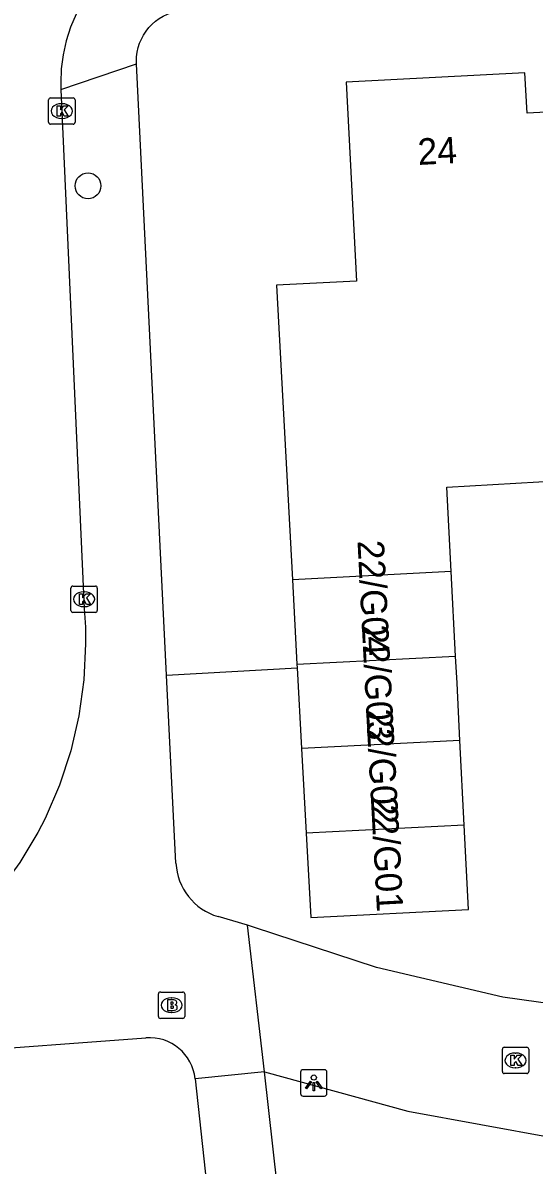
# Model space of a CAD drawing. Extents: x 161253 to 161848, y 384872 to 385383.
# Drawn here: x 161394.3 to 161413.67, y 385296.1 to 385339.43 of the extents above; entities that cross this region are included whole.
import ezdxf

# ---------------------------------------------------------------- set-up
doc = ezdxf.new("R2010")
doc.units = 0
for name, color, linetype in [('IMGEO_Boom', 7, 'Continuous'), ('IMGEO_Brandkraan', 7, 'Continuous'), ('IMGEO_Erf', 7, 'Continuous'), ('IMGEO_Kolk', 7, 'Continuous'), ('IMGEO_Lichtpunt', 7, 'Continuous'), ('IMGEO_Pand', 7, 'Continuous'), ('IMGEO_Pand_nummerreeks', 7, 'Continuous'), ('IMGEO_Rijbaan_lokaal_open', 7, 'Continuous'), ('IMGEO_Voetpad_open', 7, 'Continuous')]:
    doc.layers.add(name, color=color, linetype=linetype)

msp = doc.modelspace()

# ---------------------------------------------------------------- linework, layer by layer
at = {"layer": 'IMGEO_Boom'}
msp.add_circle((161396.765, 385333.248), 0.489, dxfattribs=at)
at = {"layer": 'IMGEO_Brandkraan'}
for p, q in [((161399.432, 385301.745), (161399.432, 385302.597)), ((161399.507, 385302.671), (161400.359, 385302.671)), ((161399.92, 385302.451), (161399.945, 385302.451)), ((161400.433, 385302.597), (161400.433, 385301.745)), ((161400.359, 385301.671), (161399.507, 385301.671)), ((161399.943, 385301.891), (161399.918, 385301.891))]:
    msp.add_line(p, q, dxfattribs=at)
for points in [[(161399.432, 385301.745), (161399.432, 385302.597)], [(161399.507, 385302.671), (161400.359, 385302.671)], [(161400.433, 385302.597), (161400.433, 385301.745)], [(161399.78, 385302.371), (161399.78, 385301.971), (161399.993, 385301.971)], [(161400.011, 385302.371), (161399.78, 385302.371)], [(161399.959, 385302.29), (161399.905, 385302.29), (161399.905, 385302.214)], [(161399.905, 385302.214), (161399.958, 385302.214)], [(161399.967, 385302.138), (161399.905, 385302.138), (161399.905, 385302.057)], [(161399.905, 385302.057), (161399.967, 385302.057)], [(161400.359, 385301.671), (161399.507, 385301.671)]]:
    msp.add_lwpolyline(points, dxfattribs=at)
for centre, radius, start, end in [((161399.509, 385302.595), 0.0765, 91.552, 178.448), ((161399.509, 385302.595), 0.0765, 91.552, 178.448), ((161400.357, 385302.595), 0.0765, 1.552, 88.448), ((161400.357, 385302.595), 0.0765, 1.552, 88.448), ((161399.96, 385302.252), 0.0379, 267.8285, 90.9355), ((161399.968, 385302.097), 0.0404, 269.8759, 90.5077), ((161399.999, 385302.222), 0.251, 268.6676, 293.5347), ((161400.015, 385302.226), 0.145, 59.4692, 91.5367), ((161400.04, 385302.273), 0.0922, 285.5137, 58.1501), ((161400.045, 385302.081), 0.105, 301.3115, 78.989), ((161399.509, 385301.747), 0.0765, 181.552, 268.448), ((161399.509, 385301.747), 0.0765, 181.552, 268.448), ((161400.357, 385301.747), 0.0765, 271.552, 358.448), ((161400.357, 385301.747), 0.0765, 271.552, 358.448)]:
    msp.add_arc(centre, radius, start, end, dxfattribs=at)
for centre, major_axis, ratio, start_param, end_param in [((161399.919, 385302.171), (-0.387, 0.002), 0.722429, 4.712389, 7.853982), ((161399.944, 385302.171), (-0.39, 0.002), 0.717154, 1.570796, 4.712389)]:
    msp.add_ellipse(centre, major_axis=major_axis, ratio=ratio, start_param=start_param, end_param=end_param, dxfattribs=at)
at = {"layer": 'IMGEO_Erf'}
msp.add_lwpolyline([(161399.745, 385314.686), (161404.692, 385314.964)], dxfattribs=at)
at = {"layer": 'IMGEO_Kolk'}
for p, q in [((161395.273, 385335.659), (161395.273, 385336.511)), ((161395.348, 385336.585), (161396.2, 385336.585)), ((161395.761, 385336.365), (161395.786, 385336.365)), ((161396.274, 385336.511), (161396.274, 385335.659)), ((161395.784, 385335.805), (161395.759, 385335.805)), ((161396.2, 385335.585), (161395.348, 385335.585)), ((161396.191, 385318.068), (161397.043, 385318.068)), ((161396.116, 385317.142), (161396.116, 385317.994)), ((161396.604, 385317.848), (161396.629, 385317.848)), ((161397.117, 385317.994), (161397.117, 385317.142)), ((161396.627, 385317.288), (161396.602, 385317.288)), ((161397.043, 385317.068), (161396.191, 385317.068)), ((161412.466, 385299.651), (161412.466, 385300.503)), ((161412.541, 385300.577), (161413.393, 385300.577)), ((161412.954, 385300.357), (161412.979, 385300.357)), ((161413.467, 385300.503), (161413.467, 385299.651)), ((161413.393, 385299.577), (161412.541, 385299.577)), ((161412.977, 385299.797), (161412.952, 385299.797))]:
    msp.add_line(p, q, dxfattribs=at)
for points in [[(161395.273, 385335.659), (161395.273, 385336.511)], [(161395.348, 385336.585), (161396.2, 385336.585)], [(161395.594, 385336.285), (161395.717, 385336.285), (161395.717, 385336.134), (161395.847, 385336.285), (161396.011, 385336.285), (161395.865, 385336.134), (161396.018, 385335.885), (161395.866, 385335.885), (161395.781, 385336.049), (161395.717, 385335.982), (161395.717, 385335.885), (161395.594, 385335.885), (161395.594, 385336.285)], [(161396.274, 385336.511), (161396.274, 385335.659)], [(161396.2, 385335.585), (161395.348, 385335.585)], [(161396.191, 385318.068), (161397.043, 385318.068)], [(161396.116, 385317.142), (161396.116, 385317.994)], [(161396.437, 385317.768), (161396.56, 385317.768), (161396.56, 385317.617), (161396.69, 385317.768), (161396.854, 385317.768), (161396.708, 385317.617), (161396.861, 385317.368), (161396.709, 385317.368), (161396.624, 385317.532), (161396.56, 385317.465), (161396.56, 385317.368), (161396.437, 385317.368), (161396.437, 385317.768)], [(161397.117, 385317.994), (161397.117, 385317.142)], [(161397.043, 385317.068), (161396.191, 385317.068)], [(161412.466, 385299.651), (161412.466, 385300.503)], [(161412.541, 385300.577), (161413.393, 385300.577)], [(161412.787, 385300.277), (161412.91, 385300.277), (161412.91, 385300.126), (161413.04, 385300.277), (161413.204, 385300.277), (161413.058, 385300.126), (161413.211, 385299.877), (161413.059, 385299.877), (161412.974, 385300.041), (161412.91, 385299.974), (161412.91, 385299.877), (161412.787, 385299.877), (161412.787, 385300.277)], [(161413.467, 385300.503), (161413.467, 385299.651)], [(161413.393, 385299.577), (161412.541, 385299.577)]]:
    msp.add_lwpolyline(points, dxfattribs=at)
for centre, start, end in [((161395.35, 385336.509), 91.552, 178.448), ((161395.35, 385336.509), 91.552, 178.448), ((161396.198, 385336.509), 1.552, 88.448), ((161396.198, 385336.509), 1.552, 88.448), ((161395.35, 385335.661), 181.552, 268.448), ((161395.35, 385335.661), 181.552, 268.448), ((161396.198, 385335.661), 271.552, 358.448), ((161396.198, 385335.661), 271.552, 358.448), ((161396.193, 385317.992), 91.552, 178.448), ((161396.193, 385317.992), 91.552, 178.448), ((161397.041, 385317.992), 1.552, 88.448), ((161397.041, 385317.992), 1.552, 88.448), ((161396.193, 385317.144), 181.552, 268.448), ((161396.193, 385317.144), 181.552, 268.448), ((161397.041, 385317.144), 271.552, 358.448), ((161397.041, 385317.144), 271.552, 358.448), ((161412.543, 385300.501), 91.552, 178.448), ((161412.543, 385300.501), 91.552, 178.448), ((161413.391, 385300.501), 1.552, 88.448), ((161413.391, 385300.501), 1.552, 88.448), ((161412.543, 385299.653), 181.552, 268.448), ((161412.543, 385299.653), 181.552, 268.448), ((161413.391, 385299.653), 271.552, 358.448), ((161413.391, 385299.653), 271.552, 358.448)]:
    msp.add_arc(centre, 0.0765, start, end, dxfattribs=at)
for centre, major_axis, ratio, start_param, end_param in [((161395.76, 385336.085), (-0.387, 0.002), 0.722429, 4.712389, 7.853982), ((161395.785, 385336.085), (-0.39, 0.002), 0.717154, 1.570796, 4.712389), ((161396.603, 385317.568), (-0.387, 0.002), 0.722429, 4.712389, 7.853982), ((161396.628, 385317.568), (-0.39, 0.002), 0.717154, 1.570796, 4.712389), ((161412.953, 385300.077), (-0.387, 0.002), 0.722429, 4.712389, 7.853982), ((161412.978, 385300.077), (-0.39, 0.002), 0.717154, 1.570796, 4.712389)]:
    msp.add_ellipse(centre, major_axis=major_axis, ratio=ratio, start_param=start_param, end_param=end_param, dxfattribs=at)
at = {"layer": 'IMGEO_Lichtpunt'}
for p, q in [((161404.821, 385299.627), (161404.821, 385298.82)), ((161404.821, 385299.627), (161404.821, 385298.82)), ((161405.723, 385299.722), (161404.915, 385299.722)), ((161405.723, 385299.722), (161404.915, 385299.722)), ((161405.817, 385298.82), (161405.817, 385299.627)), ((161405.817, 385298.82), (161405.817, 385299.627)), ((161404.915, 385298.726), (161405.723, 385298.726)), ((161404.915, 385298.726), (161405.723, 385298.726))]:
    msp.add_line(p, q, dxfattribs=at)
for points in [[(161405.195, 385299.291), (161405.234, 385299.263), (161405.046, 385299.001), (161405.008, 385299.028), (161405.195, 385299.291)], [(161405.297, 385299.243), (161405.344, 385299.243), (161405.344, 385298.921), (161405.297, 385298.921), (161405.297, 385299.243)], [(161405.407, 385299.263), (161405.445, 385299.29), (161405.632, 385299.028), (161405.593, 385299), (161405.407, 385299.263)]]:
    msp.add_lwpolyline(points, dxfattribs=at)
msp.add_circle((161405.32, 385299.425), 0.0994, dxfattribs=at)
for centre, start, end in [((161404.915, 385299.627), 90, 180), ((161404.915, 385299.627), 90, 180), ((161405.723, 385299.627), 0, 90), ((161405.723, 385299.627), 0, 90), ((161404.915, 385298.82), 180, 270), ((161404.915, 385298.82), 180, 270), ((161405.723, 385298.82), 270, 0), ((161405.723, 385298.82), 270, 360)]:
    msp.add_arc(centre, 0.0946, start, end, dxfattribs=at)
at = {"layer": 'IMGEO_Pand'}
for points in [[(161417.772, 385336.233), (161413.405, 385336.002), (161413.324, 385337.537), (161406.547, 385337.179), (161406.945, 385329.635), (161403.906, 385329.475), (161404.511, 385318.31)], [(161410.531, 385318.619), (161410.366, 385321.824), (161415.587, 385322.128), (161415.383, 385325.643), (161416.466, 385325.699), (161416.302, 385328.911)], [(161410.531, 385318.619), (161404.511, 385318.31)], [(161410.695, 385315.414), (161410.531, 385318.619)], [(161404.511, 385318.31), (161404.684, 385315.106)], [(161404.684, 385315.106), (161410.695, 385315.414)], [(161410.86, 385312.21), (161410.748, 385314.385), (161410.695, 385315.414)], [(161404.684, 385315.106), (161404.692, 385314.964)], [(161404.692, 385314.964), (161404.858, 385311.901)], [(161410.86, 385312.21), (161404.858, 385311.901)], [(161411.024, 385309.005), (161410.86, 385312.21)], [(161404.858, 385311.901), (161405.031, 385308.697)], [(161411.024, 385309.005), (161405.031, 385308.697)], [(161405.031, 385308.697), (161405.205, 385305.492), (161411.189, 385305.8), (161411.024, 385309.005)]]:
    msp.add_lwpolyline(points, dxfattribs=at)
at = {"layer": 'IMGEO_Rijbaan_lokaal_open'}
for points in [[(161401.421, 385343.184), (161400.886, 385343.131), (161400.357, 385343.03), (161399.84, 385342.883), (161399.338, 385342.69), (161398.855, 385342.452), (161398.395, 385342.173), (161397.962, 385341.854), (161397.559, 385341.497), (161397.19, 385341.105), (161396.857, 385340.683), (161396.563, 385340.232), (161396.311, 385339.757), (161396.102, 385339.261), (161395.939, 385338.748), (161395.822, 385338.223), (161395.752, 385337.69), (161395.73, 385337.152), (161395.736, 385336.901)], [(161395.736, 385336.901), (161396.614, 385317.218), (161396.664, 385316.508), (161396.675, 385315.878), (161396.609, 385314.509), (161396.42, 385313.152), (161396.112, 385311.817), (161395.685, 385310.515), (161395.144, 385309.256), (161394.868, 385308.726), (161394.178, 385307.586), (161393.388, 385306.512), (161392.505, 385305.512), (161391.537, 385304.596)], [(161432.821, 385315.408), (161433.495, 385302.03), (161425.328, 385301.515), (161423.54, 385301.396), (161421.316, 385301.428), (161419.104, 385301.658), (161417.343, 385301.797), (161412.483, 385302.481), (161407.703, 385303.597), (161403.042, 385305.135), (161402.809, 385305.204)], [(161403.458, 385299.646), (161402.809, 385305.204)], [(161403.458, 385299.646), (161408.88, 385298.145), (161414.415, 385297.134), (161414.509, 385297.121), (161418.051, 385296.604), (161421.626, 385296.405), (161424.736, 385296.492), (161445.597, 385297.541), (161445.594, 385298.092)]]:
    msp.add_lwpolyline(points, dxfattribs=at)
at = {"layer": 'IMGEO_Voetpad_open'}
for points in [[(161398.601, 385337.878), (161398.599, 385337.973), (161398.606, 385338.147), (161398.629, 385338.319), (161398.668, 385338.489), (161398.721, 385338.654), (161398.789, 385338.815), (161398.871, 385338.968), (161398.967, 385339.113), (161399.075, 385339.25), (161399.195, 385339.376), (161399.325, 385339.491), (161399.466, 385339.593), (161399.615, 385339.683), (161399.771, 385339.759), (161399.933, 385339.821), (161400.101, 385339.868), (161400.272, 385339.9), (161400.445, 385339.917), (161470.763, 385343.422)], [(161395.736, 385336.901), (161398.601, 385337.878)], [(161399.745, 385314.686), (161398.601, 385337.878)], [(161400.097, 385307.562), (161399.745, 385314.686)], [(161402.809, 385305.204), (161401.692, 385305.534)], [(161373.799, 385293.574), (161391.455, 385300.374), (161398.96, 385300.934)], [(161403.458, 385299.646), (161400.82, 385299.379)], [(161413.061, 385212.221), (161409.014, 385250), (161403.458, 385299.646)], [(161400.82, 385299.379), (161406.165, 385250), (161411.781, 385198.48), (161413.106, 385185.96)]]:
    msp.add_lwpolyline(points, dxfattribs=at)
for centre, radius, start, end in [((161402.323, 385307.672), 2.229, 182.8172, 253.5521), ((161399.091, 385299.2), 1.739, 5.8969, 94.3104)]:
    msp.add_arc(centre, radius, start, end, dxfattribs=at)

# ---------------------------------------------------------------- texts
at = {"layer": 'IMGEO_Pand_nummerreeks'}
for s, rotation, p in [('24', 3.0239, (161409.283, 385334.038)), ('22/G04', 272.9402, (161406.976, 385319.784)), ('22/G03', 272.9402, (161407.141, 385316.58)), ('22/G02', 273.1003, (161407.301, 385313.388)), ('22/G01', 273.1003, (161407.481, 385310.067))]:
    msp.add_text(s, height=1, rotation=rotation, dxfattribs=at).set_placement(p)

doc.saveas('drawing.dxf')
